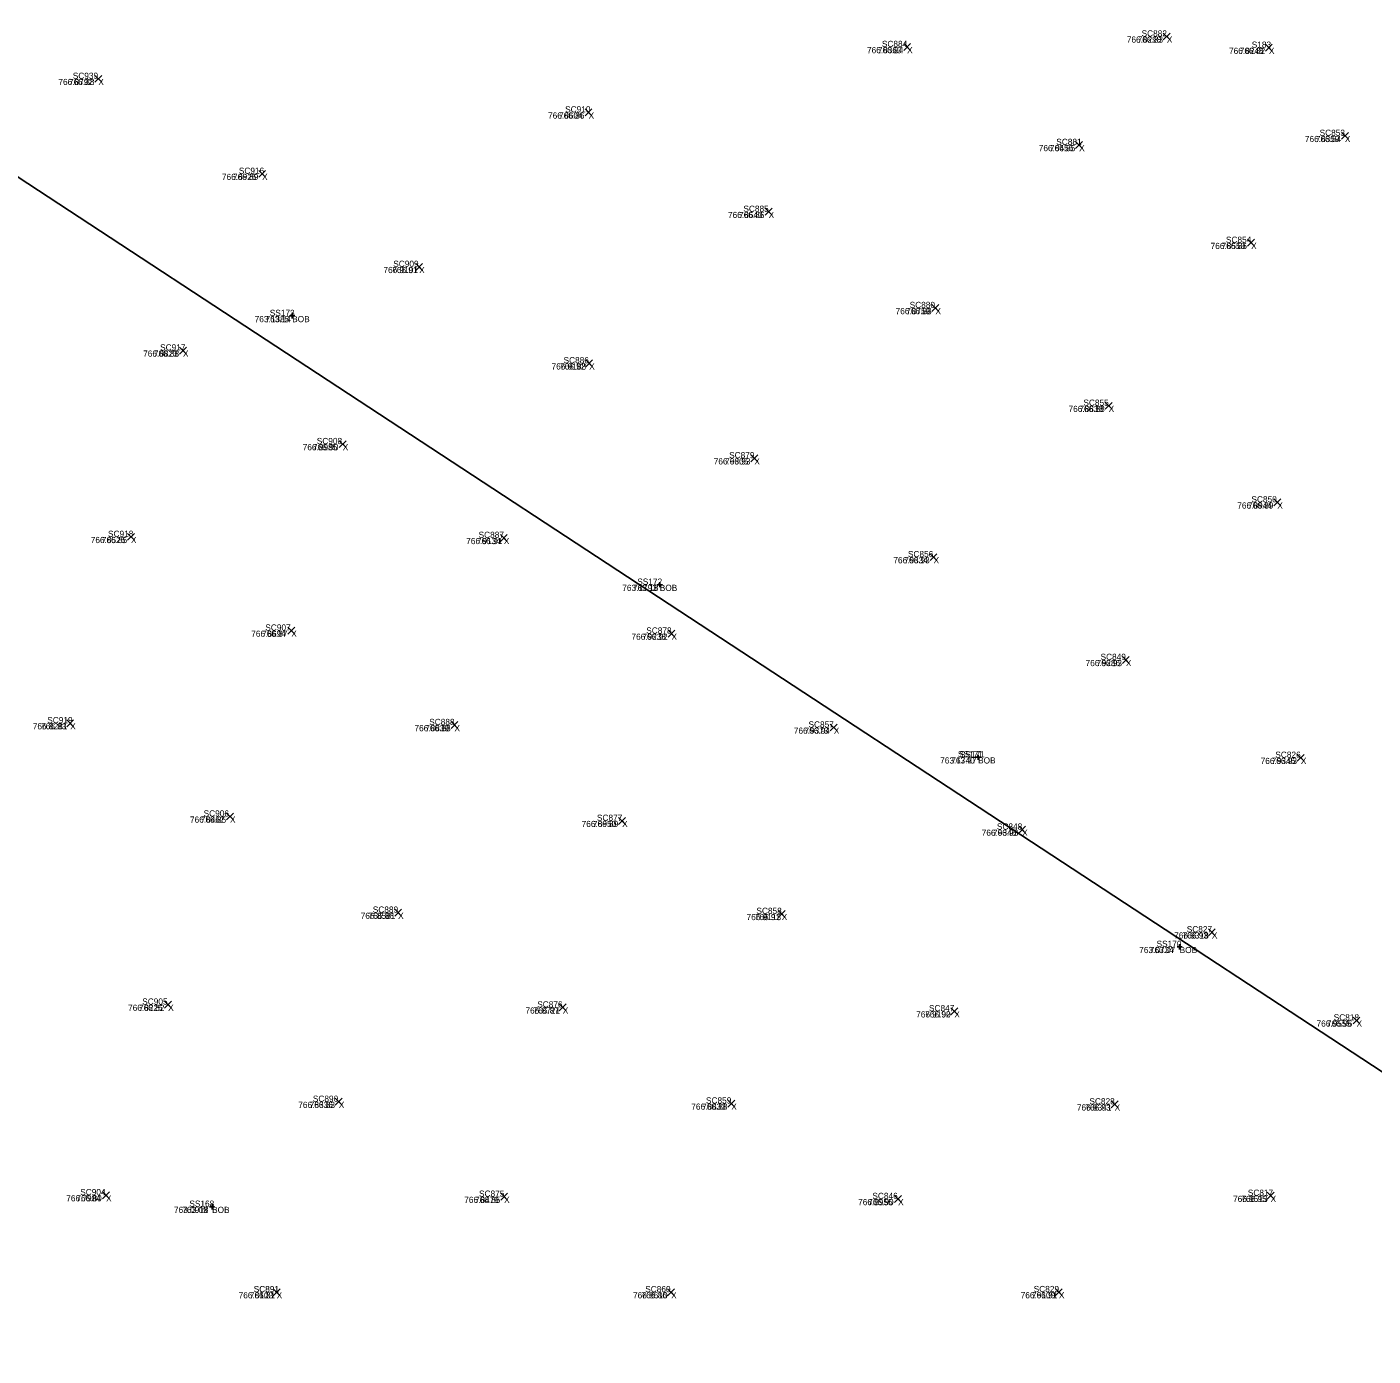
# Model space of a CAD drawing. Extents: x 1845019 to 1877956, y 680444 to 701081.
# Drawn here: x 1857591.25 to 1857604.27, y 694316.04 to 694328.91 of the extents above; entities that cross this region are included whole.
import ezdxf

# ---------------------------------------------------------------- set-up
doc = ezdxf.new("R2010")
doc.units = 0
for name, color, linetype in [('BR_X_SV_Bottom_of_Beam_Text', 7, 'Continuous'), ('SV_X_CL_Survey_20', 7, 'Continuous'), ('SV_X_Random_Point', 7, 'Continuous'), ('SV_X_Text_Comment', 7, 'Continuous'), ('SV_X_Text_Elevation', 7, 'Continuous'), ('SV_X_Text_Name', 7, 'Continuous')]:
    doc.layers.add(name, color=color, linetype=linetype)

msp = doc.modelspace()

# ---------------------------------------------------------------- linework, layer by layer
at = {"layer": 'BR_X_SV_Bottom_of_Beam_Text'}
for p, q in [((1857593.79, 694326.111), (1857593.84, 694326.111)), ((1857593.79, 694326.111), (1857593.84, 694326.111)), ((1857593.815, 694326.136), (1857593.815, 694326.086)), ((1857593.815, 694326.136), (1857593.815, 694326.086)), ((1857593.815, 694326.111), (1857593.815, 694326.111)), ((1857593.815, 694326.111), (1857593.815, 694326.111)), ((1857597.347, 694323.51), (1857597.397, 694323.51)), ((1857597.347, 694323.51), (1857597.397, 694323.51)), ((1857597.372, 694323.535), (1857597.372, 694323.485)), ((1857597.372, 694323.535), (1857597.372, 694323.485)), ((1857597.372, 694323.51), (1857597.372, 694323.51)), ((1857597.372, 694323.51), (1857597.372, 694323.51)), ((1857600.427, 694321.84), (1857600.477, 694321.84)), ((1857600.427, 694321.84), (1857600.477, 694321.84)), ((1857600.452, 694321.865), (1857600.452, 694321.815)), ((1857600.452, 694321.865), (1857600.452, 694321.815)), ((1857600.452, 694321.84), (1857600.452, 694321.84)), ((1857600.452, 694321.84), (1857600.452, 694321.84)), ((1857602.377, 694320.005), (1857602.427, 694320.005)), ((1857602.377, 694320.005), (1857602.427, 694320.005)), ((1857602.402, 694320.03), (1857602.402, 694319.98)), ((1857602.402, 694320.03), (1857602.402, 694319.98)), ((1857602.402, 694320.005), (1857602.402, 694320.005)), ((1857602.402, 694320.005), (1857602.402, 694320.005)), ((1857593.015, 694317.49), (1857593.065, 694317.49)), ((1857593.015, 694317.49), (1857593.065, 694317.49)), ((1857593.04, 694317.515), (1857593.04, 694317.465)), ((1857593.04, 694317.515), (1857593.04, 694317.465)), ((1857593.04, 694317.49), (1857593.04, 694317.49)), ((1857593.04, 694317.49), (1857593.04, 694317.49))]:
    msp.add_line(p, q, dxfattribs=at)
at = {"layer": 'SV_X_CL_Survey_20'}
msp.add_line((1856038.267, 695346.314), (1858797.327, 693536.085), dxfattribs=at)
at = {"layer": 'SV_X_Random_Point'}
for p, q in [((1857602.244, 694328.783), (1857602.311, 694328.849)), ((1857602.244, 694328.849), (1857602.311, 694328.783)), ((1857602.244, 694328.783), (1857602.311, 694328.849)), ((1857602.244, 694328.849), (1857602.311, 694328.783)), ((1857599.732, 694328.681), (1857599.798, 694328.747)), ((1857599.732, 694328.747), (1857599.798, 694328.681)), ((1857599.732, 694328.681), (1857599.798, 694328.747)), ((1857599.732, 694328.747), (1857599.798, 694328.681)), ((1857603.232, 694328.674), (1857603.299, 694328.741)), ((1857603.232, 694328.741), (1857603.299, 694328.674)), ((1857603.232, 694328.674), (1857603.299, 694328.741)), ((1857603.232, 694328.741), (1857603.299, 694328.674)), ((1857591.906, 694328.373), (1857591.972, 694328.44)), ((1857591.906, 694328.44), (1857591.972, 694328.373)), ((1857591.906, 694328.373), (1857591.972, 694328.44)), ((1857591.906, 694328.44), (1857591.972, 694328.373)), ((1857596.65, 694328.048), (1857596.716, 694328.115)), ((1857596.65, 694328.115), (1857596.716, 694328.048)), ((1857596.65, 694328.048), (1857596.716, 694328.115)), ((1857596.65, 694328.115), (1857596.716, 694328.048)), ((1857603.968, 694327.821), (1857604.035, 694327.887)), ((1857603.968, 694327.887), (1857604.035, 694327.821)), ((1857603.968, 694327.821), (1857604.035, 694327.887)), ((1857603.968, 694327.887), (1857604.035, 694327.821)), ((1857601.396, 694327.733), (1857601.463, 694327.8)), ((1857601.396, 694327.8), (1857601.463, 694327.733)), ((1857601.396, 694327.733), (1857601.463, 694327.8)), ((1857601.396, 694327.8), (1857601.463, 694327.733)), ((1857593.491, 694327.453), (1857593.558, 694327.52)), ((1857593.491, 694327.52), (1857593.558, 694327.453)), ((1857593.491, 694327.453), (1857593.558, 694327.52)), ((1857593.491, 694327.52), (1857593.558, 694327.453)), ((1857598.392, 694327.086), (1857598.458, 694327.153)), ((1857598.392, 694327.153), (1857598.458, 694327.086)), ((1857598.392, 694327.086), (1857598.458, 694327.153)), ((1857598.392, 694327.153), (1857598.458, 694327.086)), ((1857603.06, 694326.786), (1857603.127, 694326.853)), ((1857603.06, 694326.853), (1857603.127, 694326.786)), ((1857603.06, 694326.786), (1857603.127, 694326.853)), ((1857603.06, 694326.853), (1857603.127, 694326.786)), ((1857595.011, 694326.552), (1857595.077, 694326.619)), ((1857595.011, 694326.619), (1857595.077, 694326.552)), ((1857595.011, 694326.552), (1857595.077, 694326.619)), ((1857595.011, 694326.619), (1857595.077, 694326.552)), ((1857600.006, 694326.155), (1857600.072, 694326.221)), ((1857600.006, 694326.221), (1857600.072, 694326.155)), ((1857600.006, 694326.155), (1857600.072, 694326.221)), ((1857600.006, 694326.221), (1857600.072, 694326.155)), ((1857592.725, 694325.743), (1857592.792, 694325.81)), ((1857592.725, 694325.81), (1857592.792, 694325.743)), ((1857592.725, 694325.743), (1857592.792, 694325.81)), ((1857592.725, 694325.81), (1857592.792, 694325.743)), ((1857596.656, 694325.62), (1857596.722, 694325.686)), ((1857596.656, 694325.686), (1857596.722, 694325.62)), ((1857596.656, 694325.62), (1857596.722, 694325.686)), ((1857596.656, 694325.686), (1857596.722, 694325.62)), ((1857601.681, 694325.208), (1857601.748, 694325.275)), ((1857601.681, 694325.275), (1857601.748, 694325.208)), ((1857601.681, 694325.208), (1857601.748, 694325.275)), ((1857601.681, 694325.275), (1857601.748, 694325.208)), ((1857594.271, 694324.838), (1857594.338, 694324.904)), ((1857594.271, 694324.904), (1857594.338, 694324.838)), ((1857594.271, 694324.838), (1857594.338, 694324.904)), ((1857594.271, 694324.904), (1857594.338, 694324.838)), ((1857598.254, 694324.7), (1857598.321, 694324.767)), ((1857598.254, 694324.767), (1857598.321, 694324.7)), ((1857598.254, 694324.7), (1857598.321, 694324.767)), ((1857598.254, 694324.767), (1857598.321, 694324.7)), ((1857603.313, 694324.274), (1857603.38, 694324.34)), ((1857603.313, 694324.34), (1857603.38, 694324.274)), ((1857603.313, 694324.274), (1857603.38, 694324.34)), ((1857603.313, 694324.34), (1857603.38, 694324.274)), ((1857592.221, 694323.94), (1857592.288, 694324.006)), ((1857592.221, 694324.006), (1857592.288, 694323.94)), ((1857592.221, 694323.94), (1857592.288, 694324.006)), ((1857592.221, 694324.006), (1857592.288, 694323.94)), ((1857595.83, 694323.93), (1857595.896, 694323.996)), ((1857595.83, 694323.996), (1857595.896, 694323.93)), ((1857595.83, 694323.93), (1857595.896, 694323.996)), ((1857595.83, 694323.996), (1857595.896, 694323.93)), ((1857599.987, 694323.743), (1857600.054, 694323.81)), ((1857599.987, 694323.81), (1857600.054, 694323.743)), ((1857599.987, 694323.743), (1857600.054, 694323.81)), ((1857599.987, 694323.81), (1857600.054, 694323.743)), ((1857593.773, 694323.033), (1857593.84, 694323.1)), ((1857593.773, 694323.1), (1857593.84, 694323.033)), ((1857593.773, 694323.033), (1857593.84, 694323.1)), ((1857593.773, 694323.1), (1857593.84, 694323.033)), ((1857597.452, 694323.004), (1857597.518, 694323.071)), ((1857597.452, 694323.071), (1857597.518, 694323.004)), ((1857597.452, 694323.004), (1857597.518, 694323.071)), ((1857597.452, 694323.071), (1857597.518, 694323.004)), ((1857601.848, 694322.749), (1857601.915, 694322.815)), ((1857601.848, 694322.815), (1857601.915, 694322.749)), ((1857601.848, 694322.749), (1857601.915, 694322.815)), ((1857601.848, 694322.815), (1857601.915, 694322.749)), ((1857591.634, 694322.136), (1857591.7, 694322.203)), ((1857591.634, 694322.203), (1857591.7, 694322.136)), ((1857591.634, 694322.136), (1857591.7, 694322.203)), ((1857591.634, 694322.203), (1857591.7, 694322.136)), ((1857595.352, 694322.119), (1857595.419, 694322.185)), ((1857595.352, 694322.185), (1857595.419, 694322.119)), ((1857595.352, 694322.119), (1857595.419, 694322.185)), ((1857595.352, 694322.185), (1857595.419, 694322.119)), ((1857599.022, 694322.095), (1857599.089, 694322.161)), ((1857599.022, 694322.161), (1857599.089, 694322.095)), ((1857599.022, 694322.095), (1857599.089, 694322.161)), ((1857599.022, 694322.161), (1857599.089, 694322.095)), ((1857603.541, 694321.801), (1857603.608, 694321.868)), ((1857603.541, 694321.868), (1857603.608, 694321.801)), ((1857603.541, 694321.801), (1857603.608, 694321.868)), ((1857603.541, 694321.868), (1857603.608, 694321.801)), ((1857593.18, 694321.234), (1857593.246, 694321.3)), ((1857593.18, 694321.3), (1857593.246, 694321.234)), ((1857593.18, 694321.234), (1857593.246, 694321.3)), ((1857593.18, 694321.3), (1857593.246, 694321.234)), ((1857596.974, 694321.191), (1857597.041, 694321.258)), ((1857596.974, 694321.258), (1857597.041, 694321.191)), ((1857596.974, 694321.191), (1857597.041, 694321.258)), ((1857596.974, 694321.258), (1857597.041, 694321.191)), ((1857600.845, 694321.107), (1857600.912, 694321.173)), ((1857600.845, 694321.173), (1857600.912, 694321.107)), ((1857600.845, 694321.107), (1857600.912, 694321.173)), ((1857600.845, 694321.173), (1857600.912, 694321.107)), ((1857594.807, 694320.303), (1857594.873, 694320.37)), ((1857594.807, 694320.37), (1857594.873, 694320.303)), ((1857594.807, 694320.303), (1857594.873, 694320.37)), ((1857594.807, 694320.37), (1857594.873, 694320.303)), ((1857598.518, 694320.291), (1857598.585, 694320.358)), ((1857598.518, 694320.358), (1857598.585, 694320.291)), ((1857598.518, 694320.291), (1857598.585, 694320.358)), ((1857598.518, 694320.358), (1857598.585, 694320.291)), ((1857602.681, 694320.113), (1857602.747, 694320.179)), ((1857602.681, 694320.179), (1857602.747, 694320.113)), ((1857602.681, 694320.113), (1857602.747, 694320.179)), ((1857602.681, 694320.179), (1857602.747, 694320.113)), ((1857592.581, 694319.413), (1857592.648, 694319.479)), ((1857592.581, 694319.479), (1857592.648, 694319.413)), ((1857592.581, 694319.413), (1857592.648, 694319.479)), ((1857592.581, 694319.479), (1857592.648, 694319.413)), ((1857596.399, 694319.386), (1857596.466, 694319.453)), ((1857596.399, 694319.453), (1857596.466, 694319.386)), ((1857596.399, 694319.386), (1857596.466, 694319.453)), ((1857596.399, 694319.453), (1857596.466, 694319.386)), ((1857600.189, 694319.348), (1857600.256, 694319.415)), ((1857600.189, 694319.415), (1857600.256, 694319.348)), ((1857600.189, 694319.348), (1857600.256, 694319.415)), ((1857600.189, 694319.415), (1857600.256, 694319.348)), ((1857604.081, 694319.259), (1857604.147, 694319.326)), ((1857604.081, 694319.326), (1857604.147, 694319.259)), ((1857604.081, 694319.259), (1857604.147, 694319.326)), ((1857604.081, 694319.326), (1857604.147, 694319.259)), ((1857594.232, 694318.473), (1857594.299, 694318.54)), ((1857594.232, 694318.54), (1857594.299, 694318.473)), ((1857594.232, 694318.473), (1857594.299, 694318.54)), ((1857594.232, 694318.54), (1857594.299, 694318.473)), ((1857598.031, 694318.455), (1857598.098, 694318.522)), ((1857598.031, 694318.522), (1857598.098, 694318.455)), ((1857598.031, 694318.455), (1857598.098, 694318.522)), ((1857598.031, 694318.522), (1857598.098, 694318.455)), ((1857601.739, 694318.448), (1857601.806, 694318.514)), ((1857601.739, 694318.514), (1857601.806, 694318.448)), ((1857601.739, 694318.448), (1857601.806, 694318.514)), ((1857601.739, 694318.514), (1857601.806, 694318.448)), ((1857591.981, 694317.568), (1857592.048, 694317.635)), ((1857591.981, 694317.635), (1857592.048, 694317.568)), ((1857591.981, 694317.568), (1857592.048, 694317.635)), ((1857591.981, 694317.635), (1857592.048, 694317.568)), ((1857595.833, 694317.554), (1857595.899, 694317.621)), ((1857595.833, 694317.621), (1857595.899, 694317.554)), ((1857595.833, 694317.554), (1857595.899, 694317.621)), ((1857595.833, 694317.621), (1857595.899, 694317.554)), ((1857599.644, 694317.532), (1857599.711, 694317.598)), ((1857599.644, 694317.598), (1857599.711, 694317.532)), ((1857599.644, 694317.532), (1857599.711, 694317.598)), ((1857599.644, 694317.598), (1857599.711, 694317.532)), ((1857603.249, 694317.563), (1857603.316, 694317.63)), ((1857603.249, 694317.63), (1857603.316, 694317.563)), ((1857603.249, 694317.563), (1857603.316, 694317.63)), ((1857603.249, 694317.63), (1857603.316, 694317.563)), ((1857593.631, 694316.629), (1857593.698, 694316.696)), ((1857593.631, 694316.696), (1857593.698, 694316.629)), ((1857593.631, 694316.629), (1857593.698, 694316.696)), ((1857593.631, 694316.696), (1857593.698, 694316.629)), ((1857597.448, 694316.629), (1857597.515, 694316.696)), ((1857597.448, 694316.696), (1857597.515, 694316.629)), ((1857597.448, 694316.629), (1857597.515, 694316.696)), ((1857597.448, 694316.696), (1857597.515, 694316.629)), ((1857601.2, 694316.631), (1857601.267, 694316.697)), ((1857601.2, 694316.697), (1857601.267, 694316.631)), ((1857601.2, 694316.631), (1857601.267, 694316.697)), ((1857601.2, 694316.697), (1857601.267, 694316.631))]:
    msp.add_line(p, q, dxfattribs=at)

# ---------------------------------------------------------------- texts
at = {"layer": 'BR_X_SV_Bottom_of_Beam_Text'}
for s, p in [('763.1385', (1857593.452, 694326.051)), ('763.14', (1857593.557, 694326.051)), ('SS173', (1857593.598, 694326.111)), ('SS173', (1857593.598, 694326.111)), ('BOB', (1857593.815, 694326.051)), ('763.1793', (1857597.009, 694323.45)), ('763.18', (1857597.113, 694323.45)), ('SS172', (1857597.154, 694323.51)), ('SS172', (1857597.154, 694323.51)), ('BOB', (1857597.372, 694323.45)), ('SS171', (1857600.257, 694321.84)), ('SS171', (1857600.274, 694321.84)), ('763.1740', (1857600.085, 694321.78)), ('763.17', (1857600.193, 694321.78)), ('BOB', (1857600.452, 694321.78)), ('SS170', (1857602.179, 694320.005)), ('SS170', (1857602.179, 694320.005)), ('763.0734', (1857602.011, 694319.945)), ('763.07', (1857602.114, 694319.945)), ('BOB', (1857602.402, 694319.945)), ('763.0918', (1857592.671, 694317.43)), ('763.09', (1857592.752, 694317.43)), ('SS168', (1857592.82, 694317.49)), ('SS168', (1857592.82, 694317.49)), ('BOB', (1857593.04, 694317.43))]:
    msp.add_text(s, height=0.06, dxfattribs=at).set_placement(p)
at = {"layer": 'SV_X_Text_Comment'}
for p in [(1857602.278, 694328.756), (1857599.765, 694328.654), (1857603.266, 694328.647), (1857591.939, 694328.346), (1857596.683, 694328.021), (1857601.43, 694327.706), (1857604.001, 694327.794), (1857593.524, 694327.427), (1857598.425, 694327.059), (1857603.094, 694326.759), (1857595.044, 694326.526), (1857600.039, 694326.128), (1857592.758, 694325.717), (1857596.689, 694325.593), (1857601.715, 694325.182), (1857594.304, 694324.811), (1857598.287, 694324.674), (1857603.347, 694324.247), (1857592.255, 694323.913), (1857595.863, 694323.903), (1857600.021, 694323.717), (1857593.806, 694323.006), (1857597.485, 694322.977), (1857601.882, 694322.722), (1857591.667, 694322.11), (1857595.385, 694322.092), (1857599.056, 694322.068), (1857603.575, 694321.775), (1857593.213, 694321.207), (1857597.008, 694321.165), (1857600.879, 694321.08), (1857594.84, 694320.276), (1857598.552, 694320.264), (1857602.714, 694320.086), (1857592.615, 694319.386), (1857596.433, 694319.359), (1857600.222, 694319.322), (1857604.114, 694319.233), (1857594.266, 694318.446), (1857598.064, 694318.429), (1857601.773, 694318.421), (1857592.014, 694317.542), (1857595.866, 694317.527), (1857603.282, 694317.536), (1857599.678, 694317.505), (1857593.665, 694316.603), (1857597.482, 694316.603), (1857601.234, 694316.604)]:
    msp.add_text('X', height=0.06, dxfattribs=at).set_placement(p)
at = {"layer": 'SV_X_Text_Elevation'}
for s, p in [('766.8298', (1857601.891, 694328.756)), ('766.83', (1857601.996, 694328.756)), ('766.8363', (1857599.377, 694328.654)), ('766.84', (1857599.483, 694328.654)), ('766.8248', (1857602.88, 694328.647)), ('766.82', (1857602.984, 694328.647)), ('766.8792', (1857591.553, 694328.346)), ('766.88', (1857591.656, 694328.346)), ('766.8604', (1857596.291, 694328.021)), ('766.86', (1857596.397, 694328.021)), ('766.8456', (1857601.039, 694327.706)), ('766.85', (1857601.147, 694327.706)), ('766.8359', (1857603.614, 694327.794)), ('766.84', (1857603.72, 694327.794)), ('766.8926', (1857593.135, 694327.427)), ('766.89', (1857593.242, 694327.427)), ('766.8640', (1857598.032, 694327.059)), ('766.86', (1857598.139, 694327.059)), ('766.8550', (1857602.702, 694326.759)), ('766.86', (1857602.808, 694326.759)), ('766.9101', (1857594.698, 694326.526)), ('766.91', (1857594.783, 694326.526)), ('766.8759', (1857599.654, 694326.128)), ('766.88', (1857599.757, 694326.128)), ('766.8823', (1857592.373, 694325.717)), ('766.88', (1857592.476, 694325.717)), ('766.9188', (1857596.325, 694325.593)), ('766.92', (1857596.407, 694325.593)), ('766.8838', (1857601.327, 694325.182)), ('766.88', (1857601.432, 694325.182)), ('766.8985', (1857593.917, 694324.811)), ('766.90', (1857594.016, 694324.811)), ('766.9305', (1857597.894, 694324.674)), ('766.93', (1857598.004, 694324.674)), ('766.8944', (1857602.96, 694324.247)), ('766.89', (1857603.064, 694324.247)), ('766.8526', (1857591.866, 694323.913)), ('766.85', (1857591.973, 694323.913)), ('766.9134', (1857595.499, 694323.903)), ('766.91', (1857595.603, 694323.903)), ('766.9334', (1857599.632, 694323.717)), ('766.93', (1857599.738, 694323.717)), ('766.8694', (1857593.419, 694323.006)), ('766.87', (1857593.524, 694323.006)), ('766.9238', (1857597.098, 694322.977)), ('766.92', (1857597.203, 694322.977)), ('766.9286', (1857601.492, 694322.722)), ('766.93', (1857601.599, 694322.722)), ('766.8281', (1857591.305, 694322.11)), ('766.83', (1857591.385, 694322.11)), ('766.8839', (1857594.998, 694322.092)), ('766.88', (1857595.103, 694322.092)), ('766.9373', (1857598.669, 694322.068)), ('766.94', (1857598.773, 694322.068)), ('766.9345', (1857603.186, 694321.775)), ('766.93', (1857603.292, 694321.775)), ('766.8462', (1857592.826, 694321.207)), ('766.85', (1857592.931, 694321.207)), ('766.8950', (1857596.616, 694321.165)), ('766.89', (1857596.725, 694321.165)), ('766.9346', (1857600.487, 694321.08)), ('766.93', (1857600.596, 694321.08)), ('766.8581', (1857594.478, 694320.276)), ('766.86', (1857594.554, 694320.276)), ('766.9113', (1857598.212, 694320.264)), ('766.91', (1857598.291, 694320.264)), ('766.9318', (1857602.349, 694320.086)), ('766.93', (1857602.431, 694320.086)), ('766.8226', (1857592.227, 694319.386)), ('766.82', (1857592.333, 694319.386)), ('766.8721', (1857596.072, 694319.359)), ('766.87', (1857596.151, 694319.359)), ('766.9190', (1857599.853, 694319.322)), ('766.92', (1857599.94, 694319.322)), ('766.9555', (1857603.727, 694319.233)), ('766.96', (1857603.827, 694319.233)), ('766.8336', (1857593.874, 694318.446)), ('766.83', (1857593.984, 694318.446)), ('766.8833', (1857597.677, 694318.429)), ('766.88', (1857597.782, 694318.429)), ('766.9341', (1857601.408, 694318.421)), ('766.93', (1857601.49, 694318.421)), ('766.7984', (1857591.629, 694317.542)), ('766.80', (1857591.727, 694317.542)), ('766.8479', (1857595.48, 694317.527)), ('766.85', (1857595.584, 694317.527)), ('766.9513', (1857602.919, 694317.536)), ('766.95', (1857602.999, 694317.536)), ('766.8955', (1857599.291, 694317.505)), ('766.90', (1857599.389, 694317.505)), ('766.8103', (1857593.297, 694316.603)), ('766.81', (1857593.405, 694316.603)), ('766.8610', (1857597.113, 694316.603)), ('766.86', (1857597.196, 694316.603)), ('766.9109', (1857600.864, 694316.604)), ('766.91', (1857600.973, 694316.604))]:
    msp.add_text(s, height=0.06, dxfattribs=at).set_placement(p)
at = {"layer": 'SV_X_Text_Name'}
for s, p in [('SC882', (1857602.034, 694328.816)), ('SC882', (1857602.034, 694328.816)), ('SC884', (1857599.521, 694328.714)), ('SC884', (1857599.521, 694328.714)), ('S183', (1857603.1, 694328.707)), ('S183', (1857603.1, 694328.707)), ('SC939', (1857591.692, 694328.406)), ('SC939', (1857591.692, 694328.406)), ('SC910', (1857596.456, 694328.081)), ('SC910', (1857596.456, 694328.081)), ('SC853', (1857603.757, 694327.854)), ('SC853', (1857603.757, 694327.854)), ('SC881', (1857601.208, 694327.766)), ('SC881', (1857601.209, 694327.766)), ('SC916', (1857593.299, 694327.487)), ('SC916', (1857593.299, 694327.487)), ('SC885', (1857598.181, 694327.119)), ('SC885', (1857598.181, 694327.119)), ('SC854', (1857602.85, 694326.819)), ('SC854', (1857602.85, 694326.819)), ('SC909', (1857594.793, 694326.586)), ('SC909', (1857594.793, 694326.586)), ('SC880', (1857599.79, 694326.188)), ('SC880', (1857599.79, 694326.188)), ('SC917', (1857592.537, 694325.777)), ('SC917', (1857592.537, 694325.777)), ('SC886', (1857596.441, 694325.653)), ('SC886', (1857596.441, 694325.653)), ('SC855', (1857601.471, 694325.242)), ('SC855', (1857601.471, 694325.242)), ('SC908', (1857594.053, 694324.871)), ('SC908', (1857594.053, 694324.871)), ('SC879', (1857598.043, 694324.734)), ('SC879', (1857598.043, 694324.734)), ('SC850', (1857603.097, 694324.307)), ('SC850', (1857603.097, 694324.307)), ('SC918', (1857592.033, 694323.973)), ('SC918', (1857592.033, 694323.973)), ('SC887', (1857595.619, 694323.963)), ('SC887', (1857595.619, 694323.963)), ('SC856', (1857599.773, 694323.777)), ('SC856', (1857599.773, 694323.777)), ('SC907', (1857593.555, 694323.066)), ('SC907', (1857593.555, 694323.066)), ('SC878', (1857597.241, 694323.037)), ('SC878', (1857597.241, 694323.037)), ('SC849', (1857601.637, 694322.782)), ('SC849', (1857601.637, 694322.782)), ('SC919', (1857591.445, 694322.17)), ('SC919', (1857591.445, 694322.17)), ('SC888', (1857595.141, 694322.152)), ('SC888', (1857595.141, 694322.152)), ('SC857', (1857598.811, 694322.128)), ('SC857', (1857598.811, 694322.128)), ('SC826', (1857603.328, 694321.835)), ('SC826', (1857603.328, 694321.835)), ('SC906', (1857592.958, 694321.267)), ('SC906', (1857592.958, 694321.267)), ('SC877', (1857596.764, 694321.225)), ('SC877', (1857596.764, 694321.225)), ('SC848', (1857600.634, 694321.14)), ('SC848', (1857600.634, 694321.14)), ('SC889', (1857594.595, 694320.336)), ('SC889', (1857594.595, 694320.336)), ('SC858', (1857598.307, 694320.324)), ('SC858', (1857598.307, 694320.324)), ('SC827', (1857602.471, 694320.146)), ('SC827', (1857602.471, 694320.146)), ('SC905', (1857592.364, 694319.446)), ('SC905', (1857592.364, 694319.446)), ('SC876', (1857596.186, 694319.419)), ('SC876', (1857596.186, 694319.419)), ('SC847', (1857599.977, 694319.382)), ('SC847', (1857599.977, 694319.382)), ('SC818', (1857603.893, 694319.293)), ('SC818', (1857603.893, 694319.293)), ('SC890', (1857594.015, 694318.506)), ('SC890', (1857594.015, 694318.506)), ('SC859', (1857597.819, 694318.489)), ('SC859', (1857597.819, 694318.489)), ('SC828', (1857601.529, 694318.481)), ('SC828', (1857601.529, 694318.481)), ('SC904', (1857591.764, 694317.602)), ('SC904', (1857591.764, 694317.602)), ('SC875', (1857595.623, 694317.587)), ('SC875', (1857595.623, 694317.587)), ('SC846', (1857599.429, 694317.565)), ('SC846', (1857599.429, 694317.565)), ('SC817', (1857603.062, 694317.596)), ('SC817', (1857603.062, 694317.596)), ('SC891', (1857593.442, 694316.663)), ('SC891', (1857593.443, 694316.663)), ('SC860', (1857597.231, 694316.663)), ('SC860', (1857597.231, 694316.663)), ('SC829', (1857600.99, 694316.664)), ('SC829', (1857600.99, 694316.664))]:
    msp.add_text(s, height=0.06, dxfattribs=at).set_placement(p)

doc.saveas('drawing.dxf')
